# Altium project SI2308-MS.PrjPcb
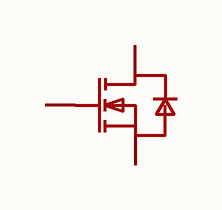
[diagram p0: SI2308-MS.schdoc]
1 sheet, 1 parts. Net scope: global (net labels, ports and power ports of the same name join across sheets).

## Sheet SI2308-MS.schdoc
size 127 x 101 mm

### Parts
Q?  si2308-ms  [SOT-23-3_L3.0-W1.7-P0.95-LS2.9-BR]  (value not drawn)

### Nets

Not connected (* = marked no-connect by the designer): Q? 1(G) 2(S) 3(D)

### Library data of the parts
Q? = si2308-ms: 数量:1个N沟道;漏源电压(Vdss):60V;连续漏极电流(Id):3A;导通电阻(RDS(on)):75mΩ@10V;耗散功率(Pd):1.25W;阈值电压(Vgs(th)):1.6V;; Manufacturer: MSKSEMI(美森科); AddInBom: yes; ModelId: 89cb27a44ab2466697082bb9fd73a7d0; ModelName: SOT-23-3L_L2.9-W1.6-H1.1-LS2.8-P0.95; ModelTransform: 114.173,110.236,0,90,0,0,0,0,0; Number: 1个N沟道; Drain to Source Voltage: 60V; Current - Continuous Drain(Id): 3A; Pd - Power Dissipation: 1.25W; Gate Threshold Voltage (Vgs(th)): 1.6V; Gate Charge(Qg): 9.3nC@10V; Input Capacitance(Ciss): 500pF; Reverse Transfer Capacitance (Crss@Vds): 16pF; Type: N沟道; Output Capacitance(Coss): 45pF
